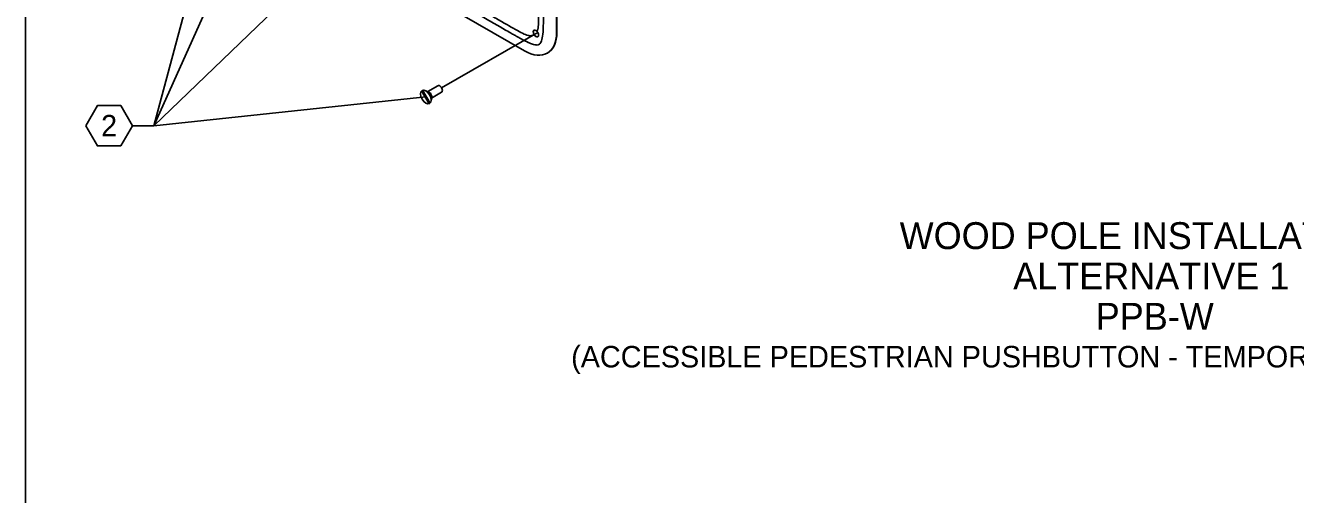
# Model space of a CAD drawing. Extents: x 99862 to 103151, y 100000 to 105076.
# Drawn here: x 99862 to 100805, y 104038 to 104386 of the extents above; entities that cross this region are included whole.
import ezdxf

# ---------------------------------------------------------------- set-up
doc = ezdxf.new("R2010")
doc.units = 0
for name, color, linetype in [('Level 1', 7, 'Continuous'), ('Level 15', 7, 'Continuous'), ('Level 16', 7, 'Continuous'), ('Level 20', 7, 'Continuous'), ('Level 40', 7, 'Continuous'), ('Level 41', 7, 'Continuous')]:
    doc.layers.add(name, color=color, linetype=linetype)

msp = doc.modelspace()

# ---------------------------------------------------------------- linework, layer by layer
at = {"layer": 'Level 1'}
msp.add_lwpolyline([(99862, 102999.5), (103151, 102999.5), (103151, 105075.5), (99862, 105075.5)], close=True, dxfattribs=at)
at = {"layer": 'Level 15'}
for p, q in [((99957.51, 104311.76), (100047.05, 104647.46)), ((99957.51, 104311.76), (100050.75, 104519.89)), ((99957.51, 104311.76), (100046.73, 104397.78)), ((99957.51, 104311.76), (100159.39, 104333.12)), ((99941.51, 104311.76), (99957.51, 104311.76))]:
    msp.add_line(p, q, dxfattribs=at)
at = {"layer": 'Level 16'}
msp.add_line((100171.13, 104339.9), (100242.53, 104381.12), dxfattribs=at)
at = {"layer": 'Level 20'}
msp.add_lwpolyline([(99906.88, 104311.76), (99915.54, 104326.75), (99932.86, 104326.75), (99941.51, 104311.76), (99932.86, 104296.76), (99915.54, 104296.76), (99906.88, 104311.76)], dxfattribs=at)
at = {"layer": 'Level 40'}
for p, q in [((100256.55, 104611.15), (100256.55, 104381.14)), ((100256.75, 104611.26), (100256.75, 104381.26)), ((100232.68, 104367.36), (100137.23, 104422.48))]:
    msp.add_line(p, q, dxfattribs=at)
for centre, major_axis, start_param, end_param in [((100232.68, 104394.92), (16.88, -29.23), 5.497787, 7.068583), ((100241.32, 104380.42), (-1.41, 2.44), 0.07077, 3.070823), ((100232.88, 104395.04), (16.88, -29.23), 6.283185, 7.068583)]:
    msp.add_ellipse(centre, major_axis=major_axis, ratio=0.57735, start_param=start_param, end_param=end_param, dxfattribs=at)
msp.add_ellipse((100241.12, 104380.31), major_axis=(-1.41, 2.44), ratio=0.57735, dxfattribs=at)
for points in [[(100231.12, 104642.4), (100183.39, 104669.95), (100135.66, 104697.51), (100119.75, 104706.7), (100119.75, 104688.33), (100119.75, 104573.32), (100119.75, 104458.32), (100119.75, 104439.95), (100135.66, 104430.76), (100183.39, 104403.21), (100231.12, 104375.65), (100247.03, 104366.46), (100247.03, 104384.83), (100247.03, 104499.84), (100247.03, 104614.84), (100247.03, 104621.81), (100243.03, 104629.33)], [(100123.73, 104497.45), (100183.39, 104463), (100243.06, 104428.56), (100243.06, 104407.84), (100243.06, 104387.13), (100243.06, 104384.06), (100241.93, 104381.94)], [(100239.71, 104379.5), (100236.19, 104377.31), (100231.12, 104380.24), (100183.39, 104407.8), (100135.66, 104435.35), (100123.73, 104442.24), (100123.73, 104456.02), (100123.73, 104476.74), (100123.73, 104497.45)]]:
    msp.add_open_spline(points, degree=4, dxfattribs=at)
at = {"layer": 'Level 41'}
for p, q in [((100168.32, 104341.52), (100160.82, 104337.19)), ((100156.27, 104337.77), (100161.85, 104328.09)), ((100156.92, 104338.14), (100162.5, 104328.46)), ((100161.46, 104336.94), (100158.77, 104338.01)), ((100163.31, 104330.14), (100163.74, 104333)), ((100163.64, 104332.32), (100171.13, 104336.65))]:
    msp.add_line(p, q, dxfattribs=at)
for centre, start_param, end_param in [((100169.73, 104339.09), 6.28318, 9.424778), ((100169.73, 104339.09), 3.141593, 3.141605), ((100161.77, 104334.49), 0.630137, 2.511455)]:
    msp.add_ellipse(centre, major_axis=(1.41, -2.44), ratio=0.57735, start_param=start_param, end_param=end_param, dxfattribs=at)
msp.add_ellipse((100159.39, 104333.12), major_axis=(-2.81, 4.87), ratio=0.57735, dxfattribs=at)

# ---------------------------------------------------------------- texts
at = {"layer": 'Level 20'}
for s, height, p in [('2', 16, (99918.21, 104303.76)), ('WOOD POLE INSTALLATION', 20, (100511.32, 104220.04)), ('ALTERNATIVE 1', 20, (100595.63, 104190.04)), ('PPB-W', 20, (100656.95, 104160.04)), ('(ACCESSIBLE PEDESTRIAN PUSHBUTTON - TEMPORARY TIMBER STRAIN POLE)', 16, (100267.33, 104132.04))]:
    msp.add_text(s, height=height, dxfattribs=at).set_placement(p)

doc.saveas('drawing.dxf')
